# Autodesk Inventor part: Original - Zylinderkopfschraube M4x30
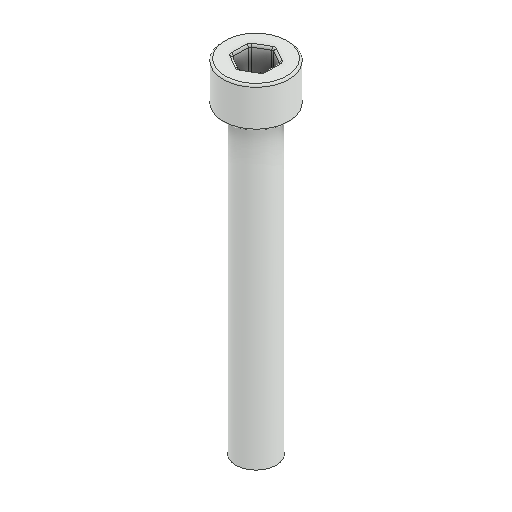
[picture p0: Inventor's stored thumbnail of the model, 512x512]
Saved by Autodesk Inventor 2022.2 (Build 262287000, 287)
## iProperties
Created: 2024-09
Part Number: Original - Zylinderkopfschraube M4x30
Material: Generico
Document SubType Name: Modeling
Designer: 18907419
Density: 1 g/cm^3
Appearance: Default
Author: 18907419
Revision Number: ANY
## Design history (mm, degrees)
feature "Verrundung3"
node "Solido1"
